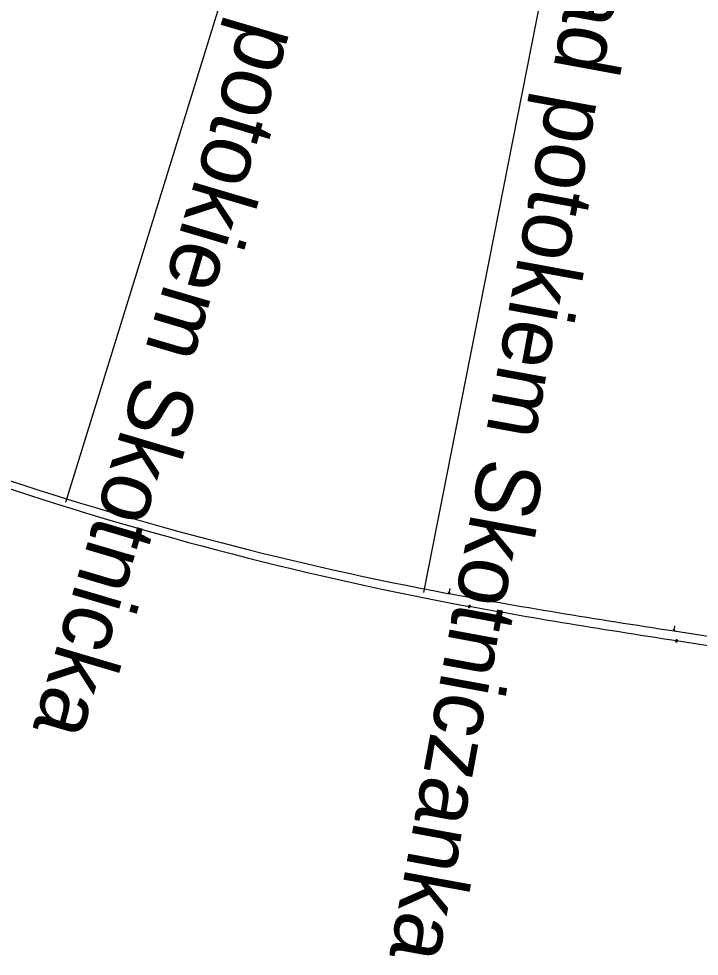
# Model space of a CAD drawing. Extents: x 6540402 to 6566579, y 5525343 to 5532423.
# Drawn here: x 6542924 to 6543297, y 5526445 to 5526958 of the extents above; entities that cross this region are included whole.
import ezdxf

# ---------------------------------------------------------------- set-up
doc = ezdxf.new("R2010")
doc.units = 0
for name, color, linetype in [('IR_ps_geometria', 7, 'Continuous'), ('TOR_PS_OPIS_T-opisy dodatkowe', 7, 'Continuous'), ('TOR_PS_OPIS_T-symbole geometrii', 7, 'Continuous'), ('TOR_PS_OPIS_T-ukresy', 7, 'Continuous'), ('TOR_PS_T-tory projektowane', 7, 'Continuous')]:
    doc.layers.add(name, color=color, linetype=linetype)

msp = doc.modelspace()

# ---------------------------------------------------------------- linework, layer by layer
at = {"layer": 'IR_ps_geometria'}
for points in [[(6543170.92, 5526636.25), (6543170.88, 5526636), (6543170.91, 5526635.99), (6543170.94, 5526635.98), (6543170.97, 5526635.96), (6543171, 5526635.94), (6543171.02, 5526635.92), (6543171.04, 5526635.9), (6543171.06, 5526635.87), (6543171.07, 5526635.84), (6543171.08, 5526635.81), (6543171.08, 5526635.77), (6543171.08, 5526635.74), (6543171.08, 5526635.71), (6543171.07, 5526635.68), (6543171.06, 5526635.65), (6543171.04, 5526635.62), (6543171.02, 5526635.59), (6543171, 5526635.57), (6543170.97, 5526635.55), (6543170.95, 5526635.53), (6543170.92, 5526635.52), (6543170.88, 5526635.51), (6543170.85, 5526635.5), (6543170.82, 5526635.5), (6543170.79, 5526635.51), (6543170.76, 5526635.52), (6543170.72, 5526635.53), (6543170.7, 5526635.54), (6543170.67, 5526635.56), (6543170.65, 5526635.59), (6543170.63, 5526635.61), (6543170.61, 5526635.64), (6543170.6, 5526635.67), (6543170.59, 5526635.7), (6543170.58, 5526635.73), (6543170.58, 5526635.77), (6543170.59, 5526635.8), (6543170.6, 5526635.83), (6543170.61, 5526635.86), (6543170.62, 5526635.89), (6543170.64, 5526635.92), (6543170.67, 5526635.94), (6543170.69, 5526635.96), (6543170.72, 5526635.98), (6543170.75, 5526635.99), (6543170.78, 5526636), (6543170.81, 5526636), (6543170.85, 5526636), (6543170.88, 5526636), (6543170.97, 5526636.49), (6543170.94, 5526636.5), (6543170.91, 5526636.51), (6543170.88, 5526636.53), (6543170.85, 5526636.55), (6543170.83, 5526636.57), (6543170.81, 5526636.6), (6543170.79, 5526636.62), (6543170.78, 5526636.65), (6543170.77, 5526636.69), (6543170.77, 5526636.72), (6543170.77, 5526636.75), (6543170.77, 5526636.78), (6543170.78, 5526636.81), (6543170.79, 5526636.84), (6543170.81, 5526636.87), (6543170.83, 5526636.9), (6543170.85, 5526636.92), (6543170.87, 5526636.94), (6543170.9, 5526636.96), (6543170.93, 5526636.97), (6543170.96, 5526636.98), (6543171, 5526636.99), (6543171.03, 5526636.99), (6543171.06, 5526636.98), (6543171.09, 5526636.97), (6543171.12, 5526636.96), (6543171.15, 5526636.95), (6543171.18, 5526636.93), (6543171.2, 5526636.9), (6543171.22, 5526636.88), (6543171.24, 5526636.85), (6543171.25, 5526636.82), (6543171.26, 5526636.79), (6543171.27, 5526636.76), (6543171.27, 5526636.72), (6543171.26, 5526636.69), (6543171.25, 5526636.66), (6543171.24, 5526636.63), (6543171.23, 5526636.6), (6543171.21, 5526636.57), (6543171.18, 5526636.55), (6543171.16, 5526636.53), (6543171.13, 5526636.51), (6543171.1, 5526636.5), (6543171.07, 5526636.49), (6543171.04, 5526636.49), (6543171, 5526636.49), (6543170.97, 5526636.49)], [(6543170.92, 5526636.25), (6543170.88, 5526636), (6543170.91, 5526635.99), (6543170.94, 5526635.98), (6543170.97, 5526635.96), (6543171, 5526635.94), (6543171.02, 5526635.92), (6543171.04, 5526635.9), (6543171.06, 5526635.87), (6543171.07, 5526635.84), (6543171.08, 5526635.81), (6543171.08, 5526635.77), (6543171.08, 5526635.74), (6543171.08, 5526635.71), (6543171.07, 5526635.68), (6543171.06, 5526635.65), (6543171.04, 5526635.62), (6543171.02, 5526635.59), (6543171, 5526635.57), (6543170.97, 5526635.55), (6543170.95, 5526635.53), (6543170.92, 5526635.52), (6543170.88, 5526635.51), (6543170.85, 5526635.5), (6543170.82, 5526635.5), (6543170.79, 5526635.51), (6543170.76, 5526635.52), (6543170.72, 5526635.53), (6543170.7, 5526635.54), (6543170.67, 5526635.56), (6543170.65, 5526635.59), (6543170.63, 5526635.61), (6543170.61, 5526635.64), (6543170.6, 5526635.67), (6543170.59, 5526635.7), (6543170.58, 5526635.73), (6543170.58, 5526635.77), (6543170.59, 5526635.8), (6543170.6, 5526635.83), (6543170.61, 5526635.86), (6543170.62, 5526635.89), (6543170.64, 5526635.92), (6543170.67, 5526635.94), (6543170.69, 5526635.96), (6543170.72, 5526635.98), (6543170.75, 5526635.99), (6543170.78, 5526636), (6543170.81, 5526636), (6543170.85, 5526636), (6543170.88, 5526636), (6543170.97, 5526636.49), (6543170.94, 5526636.5), (6543170.91, 5526636.51), (6543170.88, 5526636.53), (6543170.85, 5526636.55), (6543170.83, 5526636.57), (6543170.81, 5526636.6), (6543170.79, 5526636.62), (6543170.78, 5526636.65), (6543170.77, 5526636.69), (6543170.77, 5526636.72), (6543170.77, 5526636.75), (6543170.77, 5526636.78), (6543170.78, 5526636.81), (6543170.79, 5526636.84), (6543170.81, 5526636.87), (6543170.83, 5526636.9), (6543170.85, 5526636.92), (6543170.87, 5526636.94), (6543170.9, 5526636.96), (6543170.93, 5526636.97), (6543170.96, 5526636.98), (6543171, 5526636.99), (6543171.03, 5526636.99), (6543171.06, 5526636.98), (6543171.09, 5526636.97), (6543171.12, 5526636.96), (6543171.15, 5526636.95), (6543171.18, 5526636.93), (6543171.2, 5526636.9), (6543171.22, 5526636.88), (6543171.24, 5526636.85), (6543171.25, 5526636.82), (6543171.26, 5526636.79), (6543171.27, 5526636.76), (6543171.27, 5526636.72), (6543171.26, 5526636.69), (6543171.25, 5526636.66), (6543171.24, 5526636.63), (6543171.23, 5526636.6), (6543171.21, 5526636.57), (6543171.18, 5526636.55), (6543171.16, 5526636.53), (6543171.13, 5526636.51), (6543171.1, 5526636.5), (6543171.07, 5526636.49), (6543171.04, 5526636.49), (6543171, 5526636.49), (6543170.97, 5526636.49)], [(6543170.92, 5526636.25), (6543170.88, 5526636), (6543170.91, 5526635.99), (6543170.94, 5526635.98), (6543170.97, 5526635.96), (6543171, 5526635.94), (6543171.02, 5526635.92), (6543171.04, 5526635.9), (6543171.06, 5526635.87), (6543171.07, 5526635.84), (6543171.08, 5526635.81), (6543171.08, 5526635.77), (6543171.08, 5526635.74), (6543171.08, 5526635.71), (6543171.07, 5526635.68), (6543171.06, 5526635.65), (6543171.04, 5526635.62), (6543171.02, 5526635.59), (6543171, 5526635.57), (6543170.97, 5526635.55), (6543170.95, 5526635.53), (6543170.92, 5526635.52), (6543170.88, 5526635.51), (6543170.85, 5526635.5), (6543170.82, 5526635.5), (6543170.79, 5526635.51), (6543170.76, 5526635.52), (6543170.72, 5526635.53), (6543170.7, 5526635.54), (6543170.67, 5526635.56), (6543170.65, 5526635.59), (6543170.63, 5526635.61), (6543170.61, 5526635.64), (6543170.6, 5526635.67), (6543170.59, 5526635.7), (6543170.58, 5526635.73), (6543170.58, 5526635.77), (6543170.59, 5526635.8), (6543170.6, 5526635.83), (6543170.61, 5526635.86), (6543170.62, 5526635.89), (6543170.64, 5526635.92), (6543170.67, 5526635.94), (6543170.69, 5526635.96), (6543170.72, 5526635.98), (6543170.75, 5526635.99), (6543170.78, 5526636), (6543170.81, 5526636), (6543170.85, 5526636), (6543170.88, 5526636), (6543170.97, 5526636.49), (6543170.94, 5526636.5), (6543170.91, 5526636.51), (6543170.88, 5526636.53), (6543170.85, 5526636.55), (6543170.83, 5526636.57), (6543170.81, 5526636.6), (6543170.79, 5526636.62), (6543170.78, 5526636.65), (6543170.77, 5526636.69), (6543170.77, 5526636.72), (6543170.77, 5526636.75), (6543170.77, 5526636.78), (6543170.78, 5526636.81), (6543170.79, 5526636.84), (6543170.81, 5526636.87), (6543170.83, 5526636.9), (6543170.85, 5526636.92), (6543170.87, 5526636.94), (6543170.9, 5526636.96), (6543170.93, 5526636.97), (6543170.96, 5526636.98), (6543171, 5526636.99), (6543171.03, 5526636.99), (6543171.06, 5526636.98), (6543171.09, 5526636.97), (6543171.12, 5526636.96), (6543171.15, 5526636.95), (6543171.18, 5526636.93), (6543171.2, 5526636.9), (6543171.22, 5526636.88), (6543171.24, 5526636.85), (6543171.25, 5526636.82), (6543171.26, 5526636.79), (6543171.27, 5526636.76), (6543171.27, 5526636.72), (6543171.26, 5526636.69), (6543171.25, 5526636.66), (6543171.24, 5526636.63), (6543171.23, 5526636.6), (6543171.21, 5526636.57), (6543171.18, 5526636.55), (6543171.16, 5526636.53), (6543171.13, 5526636.51), (6543171.1, 5526636.5), (6543171.07, 5526636.49), (6543171.04, 5526636.49), (6543171, 5526636.49), (6543170.97, 5526636.49)], [(6543170.92, 5526636.25), (6543170.88, 5526636), (6543170.91, 5526635.99), (6543170.94, 5526635.98), (6543170.97, 5526635.96), (6543171, 5526635.94), (6543171.02, 5526635.92), (6543171.04, 5526635.9), (6543171.06, 5526635.87), (6543171.07, 5526635.84), (6543171.08, 5526635.81), (6543171.08, 5526635.77), (6543171.08, 5526635.74), (6543171.08, 5526635.71), (6543171.07, 5526635.68), (6543171.06, 5526635.65), (6543171.04, 5526635.62), (6543171.02, 5526635.59), (6543171, 5526635.57), (6543170.97, 5526635.55), (6543170.95, 5526635.53), (6543170.92, 5526635.52), (6543170.88, 5526635.51), (6543170.85, 5526635.5), (6543170.82, 5526635.5), (6543170.79, 5526635.51), (6543170.76, 5526635.52), (6543170.72, 5526635.53), (6543170.7, 5526635.54), (6543170.67, 5526635.56), (6543170.65, 5526635.59), (6543170.63, 5526635.61), (6543170.61, 5526635.64), (6543170.6, 5526635.67), (6543170.59, 5526635.7), (6543170.58, 5526635.73), (6543170.58, 5526635.77), (6543170.59, 5526635.8), (6543170.6, 5526635.83), (6543170.61, 5526635.86), (6543170.62, 5526635.89), (6543170.64, 5526635.92), (6543170.67, 5526635.94), (6543170.69, 5526635.96), (6543170.72, 5526635.98), (6543170.75, 5526635.99), (6543170.78, 5526636), (6543170.81, 5526636), (6543170.85, 5526636), (6543170.88, 5526636), (6543170.97, 5526636.49), (6543170.94, 5526636.5), (6543170.91, 5526636.51), (6543170.88, 5526636.53), (6543170.85, 5526636.55), (6543170.83, 5526636.57), (6543170.81, 5526636.6), (6543170.79, 5526636.62), (6543170.78, 5526636.65), (6543170.77, 5526636.69), (6543170.77, 5526636.72), (6543170.77, 5526636.75), (6543170.77, 5526636.78), (6543170.78, 5526636.81), (6543170.79, 5526636.84), (6543170.81, 5526636.87), (6543170.83, 5526636.9), (6543170.85, 5526636.92), (6543170.87, 5526636.94), (6543170.9, 5526636.96), (6543170.93, 5526636.97), (6543170.96, 5526636.98), (6543171, 5526636.99), (6543171.03, 5526636.99), (6543171.06, 5526636.98), (6543171.09, 5526636.97), (6543171.12, 5526636.96), (6543171.15, 5526636.95), (6543171.18, 5526636.93), (6543171.2, 5526636.9), (6543171.22, 5526636.88), (6543171.24, 5526636.85), (6543171.25, 5526636.82), (6543171.26, 5526636.79), (6543171.27, 5526636.76), (6543171.27, 5526636.72), (6543171.26, 5526636.69), (6543171.25, 5526636.66), (6543171.24, 5526636.63), (6543171.23, 5526636.6), (6543171.21, 5526636.57), (6543171.18, 5526636.55), (6543171.16, 5526636.53), (6543171.13, 5526636.51), (6543171.1, 5526636.5), (6543171.07, 5526636.49), (6543171.04, 5526636.49), (6543171, 5526636.49), (6543170.97, 5526636.49)], [(6543284.37, 5526617.4), (6543284.33, 5526617.16), (6543284.36, 5526617.15), (6543284.39, 5526617.14), (6543284.42, 5526617.12), (6543284.45, 5526617.1), (6543284.47, 5526617.08), (6543284.49, 5526617.06), (6543284.51, 5526617.03), (6543284.52, 5526617), (6543284.53, 5526616.97), (6543284.54, 5526616.93), (6543284.54, 5526616.9), (6543284.54, 5526616.87), (6543284.53, 5526616.84), (6543284.52, 5526616.81), (6543284.5, 5526616.78), (6543284.48, 5526616.75), (6543284.46, 5526616.73), (6543284.44, 5526616.71), (6543284.41, 5526616.69), (6543284.38, 5526616.68), (6543284.35, 5526616.67), (6543284.32, 5526616.66), (6543284.28, 5526616.66), (6543284.25, 5526616.66), (6543284.22, 5526616.67), (6543284.19, 5526616.68), (6543284.16, 5526616.69), (6543284.13, 5526616.71), (6543284.11, 5526616.74), (6543284.09, 5526616.76), (6543284.07, 5526616.79), (6543284.06, 5526616.82), (6543284.05, 5526616.85), (6543284.04, 5526616.88), (6543284.04, 5526616.91), (6543284.04, 5526616.95), (6543284.05, 5526616.98), (6543284.06, 5526617.01), (6543284.08, 5526617.04), (6543284.09, 5526617.07), (6543284.12, 5526617.09), (6543284.14, 5526617.11), (6543284.17, 5526617.13), (6543284.2, 5526617.14), (6543284.23, 5526617.15), (6543284.26, 5526617.16), (6543284.29, 5526617.16), (6543284.33, 5526617.16), (6543284.4, 5526617.65), (6543284.37, 5526617.66), (6543284.34, 5526617.67), (6543284.31, 5526617.68), (6543284.29, 5526617.7), (6543284.26, 5526617.72), (6543284.24, 5526617.75), (6543284.22, 5526617.78), (6543284.21, 5526617.81), (6543284.2, 5526617.84), (6543284.19, 5526617.87), (6543284.19, 5526617.9), (6543284.2, 5526617.93), (6543284.2, 5526617.97), (6543284.21, 5526618), (6543284.23, 5526618.03), (6543284.25, 5526618.05), (6543284.27, 5526618.08), (6543284.3, 5526618.1), (6543284.32, 5526618.12), (6543284.35, 5526618.13), (6543284.38, 5526618.14), (6543284.42, 5526618.14), (6543284.45, 5526618.15), (6543284.48, 5526618.14), (6543284.51, 5526618.14), (6543284.54, 5526618.12), (6543284.57, 5526618.11), (6543284.6, 5526618.09), (6543284.62, 5526618.07), (6543284.64, 5526618.04), (6543284.66, 5526618.02), (6543284.68, 5526617.99), (6543284.69, 5526617.96), (6543284.69, 5526617.92), (6543284.69, 5526617.89), (6543284.69, 5526617.86), (6543284.68, 5526617.83), (6543284.67, 5526617.8), (6543284.66, 5526617.77), (6543284.64, 5526617.74), (6543284.62, 5526617.72), (6543284.59, 5526617.69), (6543284.56, 5526617.68), (6543284.53, 5526617.66), (6543284.5, 5526617.65), (6543284.47, 5526617.65), (6543284.44, 5526617.65), (6543284.4, 5526617.65)], [(6543284.37, 5526617.4), (6543284.33, 5526617.16), (6543284.36, 5526617.15), (6543284.39, 5526617.14), (6543284.42, 5526617.12), (6543284.45, 5526617.1), (6543284.47, 5526617.08), (6543284.49, 5526617.06), (6543284.51, 5526617.03), (6543284.52, 5526617), (6543284.53, 5526616.97), (6543284.54, 5526616.93), (6543284.54, 5526616.9), (6543284.54, 5526616.87), (6543284.53, 5526616.84), (6543284.52, 5526616.81), (6543284.5, 5526616.78), (6543284.48, 5526616.75), (6543284.46, 5526616.73), (6543284.44, 5526616.71), (6543284.41, 5526616.69), (6543284.38, 5526616.68), (6543284.35, 5526616.67), (6543284.32, 5526616.66), (6543284.28, 5526616.66), (6543284.25, 5526616.66), (6543284.22, 5526616.67), (6543284.19, 5526616.68), (6543284.16, 5526616.69), (6543284.13, 5526616.71), (6543284.11, 5526616.74), (6543284.09, 5526616.76), (6543284.07, 5526616.79), (6543284.06, 5526616.82), (6543284.05, 5526616.85), (6543284.04, 5526616.88), (6543284.04, 5526616.91), (6543284.04, 5526616.95), (6543284.05, 5526616.98), (6543284.06, 5526617.01), (6543284.08, 5526617.04), (6543284.09, 5526617.07), (6543284.12, 5526617.09), (6543284.14, 5526617.11), (6543284.17, 5526617.13), (6543284.2, 5526617.14), (6543284.23, 5526617.15), (6543284.26, 5526617.16), (6543284.29, 5526617.16), (6543284.33, 5526617.16), (6543284.4, 5526617.65), (6543284.37, 5526617.66), (6543284.34, 5526617.67), (6543284.31, 5526617.68), (6543284.29, 5526617.7), (6543284.26, 5526617.72), (6543284.24, 5526617.75), (6543284.22, 5526617.78), (6543284.21, 5526617.81), (6543284.2, 5526617.84), (6543284.19, 5526617.87), (6543284.19, 5526617.9), (6543284.2, 5526617.93), (6543284.2, 5526617.97), (6543284.21, 5526618), (6543284.23, 5526618.03), (6543284.25, 5526618.05), (6543284.27, 5526618.08), (6543284.3, 5526618.1), (6543284.32, 5526618.12), (6543284.35, 5526618.13), (6543284.38, 5526618.14), (6543284.42, 5526618.14), (6543284.45, 5526618.15), (6543284.48, 5526618.14), (6543284.51, 5526618.14), (6543284.54, 5526618.12), (6543284.57, 5526618.11), (6543284.6, 5526618.09), (6543284.62, 5526618.07), (6543284.64, 5526618.04), (6543284.66, 5526618.02), (6543284.68, 5526617.99), (6543284.69, 5526617.96), (6543284.69, 5526617.92), (6543284.69, 5526617.89), (6543284.69, 5526617.86), (6543284.68, 5526617.83), (6543284.67, 5526617.8), (6543284.66, 5526617.77), (6543284.64, 5526617.74), (6543284.62, 5526617.72), (6543284.59, 5526617.69), (6543284.56, 5526617.68), (6543284.53, 5526617.66), (6543284.5, 5526617.65), (6543284.47, 5526617.65), (6543284.44, 5526617.65), (6543284.4, 5526617.65)], [(6543284.37, 5526617.4), (6543284.33, 5526617.16), (6543284.36, 5526617.15), (6543284.39, 5526617.14), (6543284.42, 5526617.12), (6543284.45, 5526617.1), (6543284.47, 5526617.08), (6543284.49, 5526617.06), (6543284.51, 5526617.03), (6543284.52, 5526617), (6543284.53, 5526616.97), (6543284.54, 5526616.93), (6543284.54, 5526616.9), (6543284.54, 5526616.87), (6543284.53, 5526616.84), (6543284.52, 5526616.81), (6543284.5, 5526616.78), (6543284.48, 5526616.75), (6543284.46, 5526616.73), (6543284.44, 5526616.71), (6543284.41, 5526616.69), (6543284.38, 5526616.68), (6543284.35, 5526616.67), (6543284.32, 5526616.66), (6543284.28, 5526616.66), (6543284.25, 5526616.66), (6543284.22, 5526616.67), (6543284.19, 5526616.68), (6543284.16, 5526616.69), (6543284.13, 5526616.71), (6543284.11, 5526616.74), (6543284.09, 5526616.76), (6543284.07, 5526616.79), (6543284.06, 5526616.82), (6543284.05, 5526616.85), (6543284.04, 5526616.88), (6543284.04, 5526616.91), (6543284.04, 5526616.95), (6543284.05, 5526616.98), (6543284.06, 5526617.01), (6543284.08, 5526617.04), (6543284.09, 5526617.07), (6543284.12, 5526617.09), (6543284.14, 5526617.11), (6543284.17, 5526617.13), (6543284.2, 5526617.14), (6543284.23, 5526617.15), (6543284.26, 5526617.16), (6543284.29, 5526617.16), (6543284.33, 5526617.16), (6543284.4, 5526617.65), (6543284.37, 5526617.66), (6543284.34, 5526617.67), (6543284.31, 5526617.68), (6543284.29, 5526617.7), (6543284.26, 5526617.72), (6543284.24, 5526617.75), (6543284.22, 5526617.78), (6543284.21, 5526617.81), (6543284.2, 5526617.84), (6543284.19, 5526617.87), (6543284.19, 5526617.9), (6543284.2, 5526617.93), (6543284.2, 5526617.97), (6543284.21, 5526618), (6543284.23, 5526618.03), (6543284.25, 5526618.05), (6543284.27, 5526618.08), (6543284.3, 5526618.1), (6543284.32, 5526618.12), (6543284.35, 5526618.13), (6543284.38, 5526618.14), (6543284.42, 5526618.14), (6543284.45, 5526618.15), (6543284.48, 5526618.14), (6543284.51, 5526618.14), (6543284.54, 5526618.12), (6543284.57, 5526618.11), (6543284.6, 5526618.09), (6543284.62, 5526618.07), (6543284.64, 5526618.04), (6543284.66, 5526618.02), (6543284.68, 5526617.99), (6543284.69, 5526617.96), (6543284.69, 5526617.92), (6543284.69, 5526617.89), (6543284.69, 5526617.86), (6543284.68, 5526617.83), (6543284.67, 5526617.8), (6543284.66, 5526617.77), (6543284.64, 5526617.74), (6543284.62, 5526617.72), (6543284.59, 5526617.69), (6543284.56, 5526617.68), (6543284.53, 5526617.66), (6543284.5, 5526617.65), (6543284.47, 5526617.65), (6543284.44, 5526617.65), (6543284.4, 5526617.65)], [(6543284.37, 5526617.4), (6543284.33, 5526617.16), (6543284.36, 5526617.15), (6543284.39, 5526617.14), (6543284.42, 5526617.12), (6543284.45, 5526617.1), (6543284.47, 5526617.08), (6543284.49, 5526617.06), (6543284.51, 5526617.03), (6543284.52, 5526617), (6543284.53, 5526616.97), (6543284.54, 5526616.93), (6543284.54, 5526616.9), (6543284.54, 5526616.87), (6543284.53, 5526616.84), (6543284.52, 5526616.81), (6543284.5, 5526616.78), (6543284.48, 5526616.75), (6543284.46, 5526616.73), (6543284.44, 5526616.71), (6543284.41, 5526616.69), (6543284.38, 5526616.68), (6543284.35, 5526616.67), (6543284.32, 5526616.66), (6543284.28, 5526616.66), (6543284.25, 5526616.66), (6543284.22, 5526616.67), (6543284.19, 5526616.68), (6543284.16, 5526616.69), (6543284.13, 5526616.71), (6543284.11, 5526616.74), (6543284.09, 5526616.76), (6543284.07, 5526616.79), (6543284.06, 5526616.82), (6543284.05, 5526616.85), (6543284.04, 5526616.88), (6543284.04, 5526616.91), (6543284.04, 5526616.95), (6543284.05, 5526616.98), (6543284.06, 5526617.01), (6543284.08, 5526617.04), (6543284.09, 5526617.07), (6543284.12, 5526617.09), (6543284.14, 5526617.11), (6543284.17, 5526617.13), (6543284.2, 5526617.14), (6543284.23, 5526617.15), (6543284.26, 5526617.16), (6543284.29, 5526617.16), (6543284.33, 5526617.16), (6543284.4, 5526617.65), (6543284.37, 5526617.66), (6543284.34, 5526617.67), (6543284.31, 5526617.68), (6543284.29, 5526617.7), (6543284.26, 5526617.72), (6543284.24, 5526617.75), (6543284.22, 5526617.78), (6543284.21, 5526617.81), (6543284.2, 5526617.84), (6543284.19, 5526617.87), (6543284.19, 5526617.9), (6543284.2, 5526617.93), (6543284.2, 5526617.97), (6543284.21, 5526618), (6543284.23, 5526618.03), (6543284.25, 5526618.05), (6543284.27, 5526618.08), (6543284.3, 5526618.1), (6543284.32, 5526618.12), (6543284.35, 5526618.13), (6543284.38, 5526618.14), (6543284.42, 5526618.14), (6543284.45, 5526618.15), (6543284.48, 5526618.14), (6543284.51, 5526618.14), (6543284.54, 5526618.12), (6543284.57, 5526618.11), (6543284.6, 5526618.09), (6543284.62, 5526618.07), (6543284.64, 5526618.04), (6543284.66, 5526618.02), (6543284.68, 5526617.99), (6543284.69, 5526617.96), (6543284.69, 5526617.92), (6543284.69, 5526617.89), (6543284.69, 5526617.86), (6543284.68, 5526617.83), (6543284.67, 5526617.8), (6543284.66, 5526617.77), (6543284.64, 5526617.74), (6543284.62, 5526617.72), (6543284.59, 5526617.69), (6543284.56, 5526617.68), (6543284.53, 5526617.66), (6543284.5, 5526617.65), (6543284.47, 5526617.65), (6543284.44, 5526617.65), (6543284.4, 5526617.65)]]:
    msp.add_lwpolyline(points, close=True, dxfattribs=at)
at = {"layer": 'TOR_PS_OPIS_T-opisy dodatkowe'}
for p, q in [((6543169.78, 5527405.06), (6542949.8, 5526693.28)), ((6543289.8, 5527374.87), (6543145.78, 5526643.93))]:
    msp.add_line(p, q, dxfattribs=at)
at = {"layer": 'TOR_PS_OPIS_T-symbole geometrii'}
for p, q in [((6543159.78, 5526643.27), (6543159.45, 5526644.22)), ((6543159.78, 5526643.27), (6543160.34, 5526646.22)), ((6543159.78, 5526643.27), (6543160.44, 5526644.03)), ((6543283.07, 5526622.67), (6543282.71, 5526623.6)), ((6543283.07, 5526622.67), (6543283.53, 5526625.63)), ((6543283.07, 5526622.67), (6543283.69, 5526623.44))]:
    msp.add_line(p, q, dxfattribs=at)
at = {"layer": 'TOR_PS_OPIS_T-ukresy'}
msp.add_arc((6543591.15, 5527080.65), 500, 261.1322, 261.1322, dxfattribs=at)
at = {"layer": 'TOR_PS_T-tory projektowane'}
for p, q in [((6543430.26, 5526599.7), (6543283.07, 5526622.67)), ((6543338.1, 5526609.02), (6543284.37, 5526617.4))]:
    msp.add_line(p, q, dxfattribs=at)
for points in [[(6543283.07, 5526622.67), (6543279.08, 5526623.29), (6543275.1, 5526623.91), (6543271.12, 5526624.53), (6543267.13, 5526625.15), (6543263.15, 5526625.78), (6543259.17, 5526626.4), (6543255.18, 5526627.03), (6543251.2, 5526627.66), (6543247.22, 5526628.29), (6543243.24, 5526628.93), (6543239.25, 5526629.56), (6543235.27, 5526630.2), (6543231.29, 5526630.84), (6543227.31, 5526631.49), (6543223.33, 5526632.14), (6543219.35, 5526632.79), (6543215.37, 5526633.45), (6543211.4, 5526634.12), (6543207.42, 5526634.78), (6543203.45, 5526635.46), (6543199.47, 5526636.13), (6543195.5, 5526636.82), (6543191.52, 5526637.51), (6543187.55, 5526638.2), (6543183.58, 5526638.91), (6543179.61, 5526639.62), (6543175.64, 5526640.33), (6543171.68, 5526641.06), (6543167.71, 5526641.79), (6543163.75, 5526642.53), (6543159.78, 5526643.27)], [(6543284.37, 5526617.4), (6543280.45, 5526618.01), (6543276.53, 5526618.63), (6543272.61, 5526619.24), (6543268.69, 5526619.85), (6543264.78, 5526620.46), (6543260.86, 5526621.08), (6543256.94, 5526621.7), (6543253.02, 5526622.32), (6543249.11, 5526622.94), (6543245.19, 5526623.56), (6543241.28, 5526624.19), (6543237.36, 5526624.82), (6543233.45, 5526625.45), (6543229.53, 5526626.09), (6543225.62, 5526626.73), (6543221.71, 5526627.37), (6543217.79, 5526628.02), (6543213.88, 5526628.67), (6543209.97, 5526629.33), (6543206.06, 5526629.99), (6543202.15, 5526630.66), (6543198.25, 5526631.34), (6543194.34, 5526632.02), (6543190.43, 5526632.71), (6543186.53, 5526633.4), (6543182.63, 5526634.1), (6543178.72, 5526634.81), (6543174.82, 5526635.52), (6543170.92, 5526636.25)]]:
    msp.add_lwpolyline(points, dxfattribs=at)
for centre, radius, start, end in [((6543528.2, 5528553.24), 1950, 243.81944, 259.44276), ((6543517.35, 5528529.68), 1920, 243.99505, 259.26715)]:
    msp.add_arc(centre, radius, start, end, dxfattribs=at)

# ---------------------------------------------------------------- texts
at = {"layer": 'TOR_PS_OPIS_T-opisy dodatkowe'}
for s, rotation, p in [('Wiadukt kolejowy nad potokiem Skotnicka', 253.526, (6543178.96, 5527405.6)), ('Wiadukt kolejowy nad potokiem Skotniczanka', 259.553, (6543298.87, 5527376.38))]:
    msp.add_text(s, height=35, rotation=rotation, dxfattribs=at).set_placement(p)

doc.saveas('drawing.dxf')
